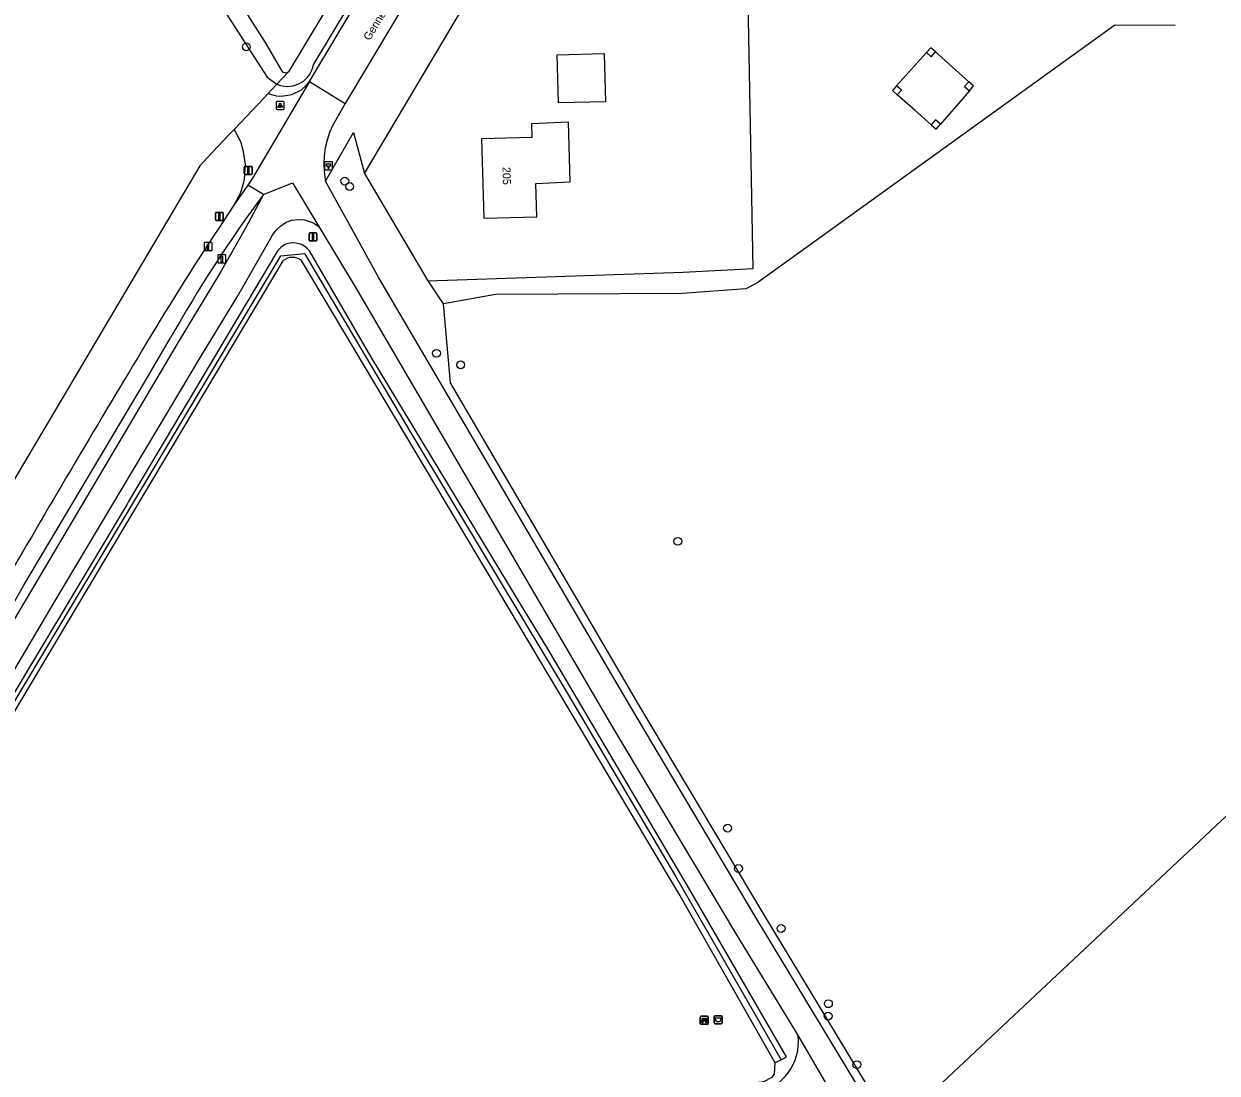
# Model space of a CAD drawing. Extents: x 160203 to 161526, y 379529 to 381797.
# Drawn here: x 160317.7 to 160466.9, y 379846.1 to 379977.3 of the extents above; entities that cross this region are included whole.
import ezdxf

# ---------------------------------------------------------------- set-up
doc = ezdxf.new("R2010")
doc.units = 0
for name, color, linetype in [('IMGEO_Afvalbak', 7, 'Continuous'), ('IMGEO_Bank', 7, 'Continuous'), ('IMGEO_Berm_groen', 7, 'Continuous'), ('IMGEO_Boom', 7, 'Continuous'), ('IMGEO_Fietspad_gesloten', 7, 'Continuous'), ('IMGEO_Grasland_agrarisch', 7, 'Continuous'), ('IMGEO_Grasland_overig', 7, 'Continuous'), ('IMGEO_Groenvoorziening', 7, 'Continuous'), ('IMGEO_Hectometerpaal', 7, 'Continuous'), ('IMGEO_Hek', 7, 'Continuous'), ('IMGEO_Hoogspanningsmast', 7, 'Continuous'), ('IMGEO_Lichtpunt', 7, 'Continuous'), ('IMGEO_Loofbos', 7, 'Continuous'), ('IMGEO_Naaldbos', 7, 'Continuous'), ('IMGEO_Openbare_ruimte_label', 7, 'Continuous'), ('IMGEO_Paal', 7, 'Continuous'), ('IMGEO_Pand', 7, 'Continuous'), ('IMGEO_Pand_nummerreeks', 7, 'Continuous'), ('IMGEO_Rijbaan_lokaal_gesloten', 7, 'Continuous'), ('IMGEO_Rijbaan_lokaal_halfverhard', 7, 'Continuous'), ('IMGEO_Rijbaan_lokaal_onverhard', 7, 'Continuous'), ('IMGEO_Rijbaan_lokaal_open', 7, 'Continuous'), ('IMGEO_Verkeersbordpaal', 7, 'Continuous'), ('IMGEO_Waterloop', 7, 'Continuous')]:
    doc.layers.add(name, color=color, linetype=linetype)

msp = doc.modelspace()

# ---------------------------------------------------------------- linework, layer by layer
at = {"layer": 'IMGEO_Afvalbak'}
for p, q in [((160404.02, 379852.39), (160404.02, 379853.19)), ((160404.02, 379853.19), (160404.02, 379852.39)), ((160404.12, 379853.29), (160404.91, 379853.29)), ((160404.91, 379853.29), (160404.12, 379853.29)), ((160405.01, 379853.19), (160405.01, 379852.39)), ((160405.01, 379852.39), (160405.01, 379853.19)), ((160404.91, 379852.29), (160404.12, 379852.29)), ((160404.12, 379852.29), (160404.91, 379852.29))]:
    msp.add_line(p, q, dxfattribs=at)
msp.add_lwpolyline([(160404.16, 379853.01), (160404.87, 379853.01), (160404.72, 379852.54), (160404.31, 379852.54), (160404.16, 379853.01)], dxfattribs=at)
for centre, start, end in [((160404.12, 379853.19), 90, 180), ((160404.12, 379853.19), 90, 180), ((160404.91, 379853.19), 0, 90), ((160404.91, 379853.19), 360, 90), ((160404.12, 379852.39), 180, 270), ((160404.12, 379852.39), 180, 270), ((160404.91, 379852.39), 270, 0), ((160404.91, 379852.39), 270, 0)]:
    msp.add_arc(centre, 0.1, start, end, dxfattribs=at)
at = {"layer": 'IMGEO_Bank'}
for p, q in [((160402.29, 379852.29), (160402.29, 379853.13)), ((160402.29, 379853.13), (160402.29, 379852.29)), ((160402.36, 379853.22), (160403.2, 379853.22)), ((160403.2, 379853.22), (160402.36, 379853.22)), ((160403.29, 379853.14), (160403.29, 379852.3)), ((160403.29, 379852.3), (160403.29, 379853.14)), ((160403.21, 379852.22), (160402.37, 379852.22)), ((160402.37, 379852.22), (160403.21, 379852.22)), ((160402.98, 379852.62), (160402.59, 379852.62)), ((160402.6, 379852.72), (160402.6, 379852.83)), ((160402.64, 379852.83), (160402.64, 379852.72)), ((160402.93, 379852.84), (160402.65, 379852.84)), ((160402.65, 379852.72), (160402.93, 379852.72)), ((160402.94, 379852.72), (160402.94, 379852.83)), ((160402.98, 379852.83), (160402.98, 379852.72))]:
    msp.add_line(p, q, dxfattribs=at)
for points in [[(160402.54, 379852.62), (160402.39, 379852.62), (160402.5, 379852.72), (160402.59, 379852.72)], [(160402.59, 379852.84), (160402.5, 379852.84), (160402.5, 379853), (160403.07, 379853), (160403.07, 379852.84), (160402.99, 379852.84)], [(160402.59, 379852.61), (160402.59, 379852.4), (160402.54, 379852.4), (160402.54, 379852.61)], [(160402.99, 379852.72), (160403.07, 379852.72), (160403.18, 379852.62), (160403.04, 379852.62)], [(160403.03, 379852.61), (160403.03, 379852.4), (160402.99, 379852.4), (160402.99, 379852.61)]]:
    msp.add_lwpolyline(points, dxfattribs=at)
for centre, radius, start, end in [((160402.37, 379853.14), 0.0779, 92.4484, 184.2845), ((160402.37, 379853.14), 0.0779, 92.4484, 184.2845), ((160403.21, 379853.14), 0.0779, 2.4484, 94.2845), ((160403.21, 379853.14), 0.0779, 2.4484, 94.2845), ((160402.37, 379852.3), 0.0779, 182.4484, 274.2845), ((160402.37, 379852.3), 0.0779, 182.4484, 274.2845), ((160402.54, 379852.61), 0.00671, 2.8957, 87.1043), ((160402.59, 379852.83), 0.00671, 2.8957, 87.1043), ((160402.59, 379852.72), 0.00671, 272.8957, 357.1043), ((160402.59, 379852.61), 0.00671, 92.8957, 177.1043), ((160402.65, 379852.83), 0.00671, 92.8957, 177.1043), ((160402.65, 379852.72), 0.00671, 182.8957, 267.1043), ((160402.93, 379852.83), 0.00671, 2.8957, 87.1043), ((160402.93, 379852.72), 0.00671, 272.8957, 357.1043), ((160402.99, 379852.83), 0.00671, 92.8957, 177.1043), ((160402.99, 379852.72), 0.00671, 182.8957, 267.1043), ((160402.98, 379852.61), 0.00671, 2.8957, 87.1043), ((160403.04, 379852.61), 0.00671, 92.8957, 177.1043), ((160403.21, 379852.3), 0.0779, 272.4484, 4.2845), ((160403.21, 379852.3), 0.0779, 272.4484, 4.2845)]:
    msp.add_arc(centre, radius, start, end, dxfattribs=at)
at = {"layer": 'IMGEO_Berm_groen'}
for points in [[(160360.33, 379958.58), (160382.33, 379995.65)], [(160348.28, 379968.57), (160349.28, 379968.28), (160349.93, 379968.22), (160351.24, 379968.42), (160352.43, 379969.02), (160353.08, 379969.61), (160353.43, 379970.05)], [(160349.37, 379969.72), (160348.7, 379969.01), (160348.28, 379968.57)], [(160355.43, 379957.61), (160358.93, 379963.68), (160360.33, 379958.58)]]:
    msp.add_lwpolyline(points, dxfattribs=at)
at = {"layer": 'IMGEO_Boom'}
for centre in [(160345.55, 379974.39), (160357.85, 379957.61), (160358.46, 379956.93), (160369.31, 379936.09), (160372.33, 379934.65), (160399.48, 379912.59), (160405.69, 379876.74), (160407.06, 379871.69), (160412.39, 379864.2), (160418.3, 379854.79), (160418.26, 379853.24), (160421.86, 379847.18)]:
    msp.add_circle(centre, 0.489, dxfattribs=at)
at = {"layer": 'IMGEO_Fietspad_gesloten'}
for points in [[(160345.72, 379957.12), (160343.99, 379954.59)], [(160334.19, 379939.24), (160333.69, 379938.42)], [(160317.74, 379907.1), (160332.84, 379932.52), (160336.07, 379938.01)]]:
    msp.add_lwpolyline(points, dxfattribs=at)
for centre, radius, start, end in [((160633.93, 379758.64), 349.94, 145.9484, 148.9301), ((160487.24, 379852.9), 173.48, 143.5655, 150.6206), ((162045.74, 378904.9), 1999.82, 148.88178, 149.88066), ((159620.75, 380295.57), 797.94, 328.33041, 330.86665)]:
    msp.add_arc(centre, radius, start, end, dxfattribs=at)
at = {"layer": 'IMGEO_Grasland_agrarisch'}
msp.add_lwpolyline([(160348.28, 379968.57), (160347.68, 379967.93), (160344.8, 379964.89), (160344.03, 379964.08)], dxfattribs=at)
at = {"layer": 'IMGEO_Grasland_overig'}
for points in [[(160368.22, 379945.15), (160400.15, 379946.25), (160408.91, 379946.67), (160407.99, 379995.8), (160400.24, 379995.97), (160382.33, 379995.65)], [(160576.07, 379979.7), (160426.4, 379839.14)], [(160426.83, 379969.52), (160430.56, 379973.7)], [(160431.69, 379973.76), (160435.85, 379970.04)], [(160431.16, 379964.64), (160429.14, 379966.42), (160426.89, 379968.4)], [(160435.92, 379968.9), (160432.29, 379964.72)], [(160368.22, 379945.15), (160370.16, 379942.26), (160371, 379932.38), (160383.71, 379910.71), (160394.58, 379892.15), (160410.1, 379866.11), (160426.4, 379839.14)], [(160412.38, 379847.79), (160411.66, 379847.42)]]:
    msp.add_lwpolyline(points, dxfattribs=at)
at = {"layer": 'IMGEO_Groenvoorziening'}
msp.add_lwpolyline([(160360.33, 379958.58), (160368.22, 379945.15)], dxfattribs=at)
at = {"layer": 'IMGEO_Hectometerpaal'}
for p, q in [((160355.33, 379959.95), (160355.33, 379959.11)), ((160355.33, 379959.95), (160355.33, 379959.11)), ((160356.24, 379960.04), (160355.4, 379960.04)), ((160356.24, 379960.04), (160355.4, 379960.04)), ((160355.41, 379959.04), (160356.25, 379959.04)), ((160355.41, 379959.04), (160356.25, 379959.04)), ((160356.33, 379959.12), (160356.33, 379959.96)), ((160356.33, 379959.12), (160356.33, 379959.96))]:
    msp.add_line(p, q, dxfattribs=at)
msp.add_lwpolyline([(160355.85, 379959.18), (160355.79, 379959.18), (160355.79, 379959.49), (160355.57, 379959.49), (160355.57, 379959.75), (160356.07, 379959.75), (160356.07, 379959.49), (160355.85, 379959.49), (160355.85, 379959.18)], dxfattribs=at)
for centre, start, end in [((160355.41, 379959.96), 92.4484, 184.2845), ((160355.41, 379959.96), 92.4484, 184.2845), ((160355.41, 379959.12), 182.4484, 274.2845), ((160355.41, 379959.12), 182.4484, 274.2845), ((160356.25, 379959.96), 2.4484, 94.2845), ((160356.25, 379959.96), 2.4484, 94.2845), ((160356.25, 379959.12), 272.4484, 4.2845), ((160356.25, 379959.12), 272.4484, 4.2845)]:
    msp.add_arc(centre, 0.0779, start, end, dxfattribs=at)
at = {"layer": 'IMGEO_Hek'}
for points in [[(160461.66, 379977.08), (160454.11, 379977.11), (160414.7, 379948.7)], [(160349.37, 379969.72), (160350.83, 379971.26)], [(160348.28, 379968.57), (160348.7, 379969.01), (160349.37, 379969.72)], [(160344.03, 379964.08), (160344.8, 379964.89), (160347.68, 379967.93), (160348.28, 379968.57)], [(160339.72, 379959.52), (160340.64, 379960.5), (160343.37, 379963.38), (160344.03, 379964.08)], [(160414.7, 379948.7), (160409.37, 379944.86), (160407.99, 379944.15), (160400.02, 379943.55), (160376.68, 379943.45), (160370.9, 379942.4), (160370.16, 379942.26)]]:
    msp.add_lwpolyline(points, dxfattribs=at)
at = {"layer": 'IMGEO_Hoogspanningsmast'}
for points in [[(160431.69, 379973.76), (160431.1, 379974.29), (160430.56, 379973.7)], [(160430.56, 379973.7), (160431.16, 379973.16), (160431.69, 379973.76)], [(160426.83, 379969.52), (160426.29, 379968.92), (160426.89, 379968.4)], [(160426.89, 379968.4), (160427.43, 379968.99), (160426.83, 379969.52)], [(160435.85, 379970.04), (160435.33, 379969.43), (160435.92, 379968.9)], [(160435.92, 379968.9), (160436.45, 379969.5), (160435.85, 379970.04)], [(160432.29, 379964.72), (160431.68, 379965.25), (160431.16, 379964.64)], [(160431.16, 379964.64), (160431.76, 379964.11), (160432.29, 379964.72)]]:
    msp.add_lwpolyline(points, dxfattribs=at)
at = {"layer": 'IMGEO_Lichtpunt'}
for p, q in [((160349.27, 379967.46), (160349.27, 379966.65)), ((160349.27, 379967.46), (160349.27, 379966.65)), ((160350.17, 379967.55), (160349.36, 379967.55)), ((160350.17, 379967.55), (160349.36, 379967.55)), ((160349.36, 379966.55), (160350.17, 379966.55)), ((160349.36, 379966.55), (160350.17, 379966.55)), ((160350.27, 379966.65), (160350.27, 379967.46)), ((160350.27, 379966.65), (160350.27, 379967.46))]:
    msp.add_line(p, q, dxfattribs=at)
for points in [[(160349.64, 379967.12), (160349.68, 379967.09), (160349.5, 379966.83), (160349.46, 379966.86), (160349.64, 379967.12)], [(160349.75, 379967.07), (160349.79, 379967.07), (160349.79, 379966.75), (160349.75, 379966.75), (160349.75, 379967.07)], [(160349.86, 379967.09), (160349.89, 379967.12), (160350.08, 379966.86), (160350.04, 379966.83), (160349.86, 379967.09)]]:
    msp.add_lwpolyline(points, dxfattribs=at)
msp.add_circle((160349.77, 379967.25), 0.0994, dxfattribs=at)
for centre, start, end in [((160349.36, 379967.46), 90, 180), ((160349.36, 379967.46), 90, 180), ((160349.36, 379966.65), 180, 270), ((160349.36, 379966.65), 180, 270), ((160350.17, 379967.46), 0, 90), ((160350.17, 379967.46), 0, 90), ((160350.17, 379966.65), 270, 0), ((160350.17, 379966.65), 270, 360)]:
    msp.add_arc(centre, 0.0946, start, end, dxfattribs=at)
at = {"layer": 'IMGEO_Loofbos'}
for points in [[(160344.03, 379964.08), (160343.37, 379963.38), (160340.64, 379960.5), (160339.72, 379959.52), (160309.99, 379909.32), (160298.15, 379889.57), (160271.43, 379843.62), (160269.94, 379840.82), (160269.1, 379840.82)], [(160344.03, 379964.08), (160344.58, 379963.06), (160344.85, 379962.42), (160345.12, 379961.53), (160345.38, 379959.7), (160345.26, 379957.86), (160345.05, 379956.96), (160344.76, 379956.08), (160343.99, 379954.59)]]:
    msp.add_lwpolyline(points, dxfattribs=at)
at = {"layer": 'IMGEO_Naaldbos'}
for points in [[(160350.12, 379947.64), (160330.19, 379914.23), (160290.49, 379847.67), (160289.95, 379848.06)], [(160411.66, 379847.42), (160399.59, 379868.58), (160378.38, 379904.17), (160352.45, 379947.67)], [(160289.38, 379848.46), (160285.52, 379842.88), (160285.39, 379842.42), (160285.36, 379841.67), (160285.4, 379841.12), (160285.57, 379840.56), (160286.32, 379839.16), (160293.26, 379839.13), (160321.57, 379840.37), (160326.56, 379840.64), (160395.84, 379844.33), (160408.84, 379844.89), (160410.21, 379845.08), (160411.28, 379845.6), (160411.57, 379846), (160411.66, 379847.42)]]:
    msp.add_lwpolyline(points, dxfattribs=at)
msp.add_arc((160351.3, 379946.26), 1.82, 50.9338, 130.3986, dxfattribs=at)
at = {"layer": 'IMGEO_Paal'}
for p, q in [((160340.26, 379949.85), (160340.26, 379949)), ((160340.26, 379949.85), (160340.26, 379949)), ((160341.17, 379949.93), (160340.33, 379949.93)), ((160341.17, 379949.93), (160340.33, 379949.93)), ((160340.34, 379948.93), (160341.18, 379948.93)), ((160340.34, 379948.93), (160341.18, 379948.93)), ((160341.26, 379949.01), (160341.26, 379949.86)), ((160341.26, 379949.01), (160341.26, 379949.86)), ((160341.97, 379948.31), (160341.97, 379947.47)), ((160341.97, 379948.31), (160341.97, 379947.47)), ((160342.89, 379948.39), (160342.05, 379948.39)), ((160342.89, 379948.39), (160342.05, 379948.39)), ((160342.06, 379947.39), (160342.9, 379947.39)), ((160342.06, 379947.39), (160342.9, 379947.39)), ((160342.97, 379947.48), (160342.97, 379948.32)), ((160342.97, 379947.48), (160342.97, 379948.32))]:
    msp.add_line(p, q, dxfattribs=at)
for points in [[(160340.67, 379949.74), (160340.83, 379949.74), (160340.83, 379949.01), (160340.67, 379949.01), (160340.67, 379949.74)], [(160342.39, 379948.21), (160342.55, 379948.21), (160342.55, 379947.47), (160342.39, 379947.47), (160342.39, 379948.21)]]:
    msp.add_lwpolyline(points, dxfattribs=at)
for centre, start, end in [((160340.34, 379949.85), 92.4484, 184.2845), ((160340.34, 379949.85), 92.4484, 184.2845), ((160340.34, 379949.01), 182.4484, 274.2845), ((160340.34, 379949.01), 182.4484, 274.2845), ((160341.18, 379949.85), 2.4484, 94.2845), ((160341.18, 379949.85), 2.4484, 94.2845), ((160341.18, 379949.01), 272.4484, 4.2845), ((160341.18, 379949.01), 272.4484, 4.2845), ((160342.05, 379948.32), 92.4484, 184.2845), ((160342.05, 379948.32), 92.4484, 184.2845), ((160342.05, 379947.47), 182.4484, 274.2845), ((160342.05, 379947.47), 182.4484, 274.2845), ((160342.9, 379948.32), 2.4484, 94.2845), ((160342.9, 379948.32), 2.4484, 94.2845), ((160342.9, 379947.47), 272.4484, 4.2845), ((160342.9, 379947.47), 272.4484, 4.2845)]:
    msp.add_arc(centre, 0.0779, start, end, dxfattribs=at)
at = {"layer": 'IMGEO_Pand'}
for points in [[(160390.27, 379973.55), (160390.43, 379967.53), (160384.55, 379967.38), (160384.39, 379973.4), (160390.27, 379973.55)], [(160385.81, 379964.96), (160381.18, 379964.79), (160381.22, 379963.05), (160374.95, 379962.89), (160375.21, 379952.97), (160381.85, 379953.15), (160381.74, 379957.31), (160386.01, 379957.54), (160385.81, 379964.96)]]:
    msp.add_lwpolyline(points, dxfattribs=at)
at = {"layer": 'IMGEO_Rijbaan_lokaal_gesloten'}
for points in [[(160353.43, 379970.05), (160346.32, 379958), (160345.72, 379957.12)], [(160353.43, 379970.05), (160357.91, 379967.3)], [(160357.91, 379967.3), (160356.34, 379964.6), (160355.94, 379963.68), (160355.63, 379962.74), (160355.41, 379961.77), (160355.27, 379960.79), (160355.22, 379959.8), (160355.26, 379958.81), (160355.39, 379957.82), (160355.43, 379957.61)], [(160424.62, 379840.15), (160409.24, 379865.59), (160393.72, 379891.65), (160383.03, 379909.88), (160362.12, 379945.53), (160355.43, 379957.61)], [(160347.67, 379955.94), (160345.72, 379957.12)], [(160347.67, 379955.94), (160351.32, 379957.41), (160354.6, 379951.94)], [(160354.6, 379951.94), (160359.38, 379943.97), (160380.87, 379907.23), (160391.07, 379889.78), (160406.69, 379863.63), (160414.5, 379850.79)], [(160414.5, 379850.79), (160421.59, 379838.6)]]:
    msp.add_lwpolyline(points, dxfattribs=at)
at = {"layer": 'IMGEO_Rijbaan_lokaal_halfverhard'}
msp.add_arc((160408.08, 379850), 6.47, 280.2664, 6.9736, dxfattribs=at)
at = {"layer": 'IMGEO_Rijbaan_lokaal_onverhard'}
for points in [[(160347.67, 379955.94), (160345.43, 379951.75), (160342.31, 379946.22), (160337.02, 379937.5), (160318.7, 379906.49), (160300.69, 379876.22), (160281.38, 379844.94), (160279.77, 379841.98), (160277.86, 379839.2), (160275.67, 379836.64), (160273.99, 379835.07)], [(160286.85, 379837.88), (160286.07, 379838.26), (160285.42, 379838.76), (160284.88, 379839.39), (160284.49, 379840.12), (160284.26, 379840.91), (160284.2, 379841.74), (160284.43, 379842.95), (160284.79, 379843.7), (160288.19, 379849.3), (160303.47, 379874.46), (160321.52, 379904.95), (160339.94, 379935.83), (160344.47, 379943.28), (160348.83, 379950.84), (160349.27, 379951.49), (160349.84, 379952.04), (160350.51, 379952.46), (160351.25, 379952.72), (160352.03, 379952.83), (160352.82, 379952.78), (160353.94, 379952.39), (160354.6, 379951.94)]]:
    msp.add_lwpolyline(points, dxfattribs=at)
at = {"layer": 'IMGEO_Rijbaan_lokaal_open'}
for points in [[(160353.43, 379970.05), (160371.33, 380000), (160375.27, 380006.61), (160373.71, 380007.73), (160373.06, 380008.26)], [(160375.89, 379997.42), (160357.91, 379967.3)]]:
    msp.add_lwpolyline(points, dxfattribs=at)
at = {"layer": 'IMGEO_Verkeersbordpaal'}
for p, q in [((160345.29, 379958.55), (160345.29, 379959.35)), ((160345.29, 379959.35), (160345.29, 379958.55)), ((160345.39, 379959.45), (160346.18, 379959.45)), ((160346.18, 379959.45), (160345.39, 379959.45)), ((160346.28, 379959.35), (160346.28, 379958.55)), ((160346.28, 379958.55), (160346.28, 379959.35)), ((160346.18, 379958.45), (160345.39, 379958.45)), ((160345.39, 379958.45), (160346.18, 379958.45)), ((160341.67, 379952.8), (160341.67, 379953.6)), ((160341.67, 379953.6), (160341.67, 379952.8)), ((160341.77, 379953.7), (160342.56, 379953.7)), ((160342.56, 379953.7), (160341.77, 379953.7)), ((160342.66, 379953.6), (160342.66, 379952.8)), ((160342.66, 379952.8), (160342.66, 379953.6)), ((160342.56, 379952.7), (160341.77, 379952.7)), ((160341.77, 379952.7), (160342.56, 379952.7)), ((160353.38, 379950.23), (160353.38, 379951.03)), ((160353.38, 379951.03), (160353.38, 379950.23)), ((160353.48, 379951.13), (160354.27, 379951.13)), ((160354.27, 379951.13), (160353.48, 379951.13)), ((160354.27, 379950.13), (160353.48, 379950.13)), ((160353.48, 379950.13), (160354.27, 379950.13)), ((160354.37, 379951.03), (160354.37, 379950.23)), ((160354.37, 379950.23), (160354.37, 379951.03))]:
    msp.add_line(p, q, dxfattribs=at)
for points in [[(160345.71, 379959.32), (160345.86, 379959.32), (160345.86, 379958.57), (160345.71, 379958.57), (160345.71, 379959.32)], [(160342.09, 379953.58), (160342.24, 379953.58), (160342.24, 379952.83), (160342.09, 379952.83), (160342.09, 379953.58)], [(160353.8, 379951.01), (160353.95, 379951.01), (160353.95, 379950.26), (160353.8, 379950.26), (160353.8, 379951.01)]]:
    msp.add_lwpolyline(points, dxfattribs=at)
for centre, start, end in [((160345.39, 379959.35), 90, 180), ((160345.39, 379959.35), 90, 180), ((160346.18, 379959.35), 0, 90), ((160346.18, 379959.35), 360, 90), ((160345.39, 379958.55), 180, 270), ((160345.39, 379958.55), 180, 270), ((160346.18, 379958.55), 270, 0), ((160346.18, 379958.55), 270, 0), ((160341.77, 379953.6), 90, 180), ((160341.77, 379953.6), 90, 180), ((160342.56, 379953.6), 0, 90), ((160342.56, 379953.6), 360, 90), ((160341.77, 379952.8), 180, 270), ((160341.77, 379952.8), 180, 270), ((160342.56, 379952.8), 270, 0), ((160342.56, 379952.8), 270, 0), ((160353.48, 379951.03), 90, 180), ((160353.48, 379951.03), 90, 180), ((160353.48, 379950.23), 180, 270), ((160353.48, 379950.23), 180, 270), ((160354.27, 379951.03), 0, 90), ((160354.27, 379951.03), 360, 90), ((160354.27, 379950.23), 270, 0), ((160354.27, 379950.23), 270, 0)]:
    msp.add_arc(centre, 0.1, start, end, dxfattribs=at)
at = {"layer": 'IMGEO_Waterloop'}
for points in [[(160373.96, 380005.5), (160370.65, 380000), (160353.95, 379972.21)], [(160368.12, 380000), (160350.83, 379971.26), (160350.52, 379971.11), (160350.09, 379971.23), (160347.92, 379974.93), (160340.63, 379986.39), (160337.45, 379991.38)], [(160337.45, 379991.38), (160335.78, 379989.85), (160340.15, 379983.05), (160348.14, 379970.62), (160349.37, 379969.72)], [(160349.27, 379948.61), (160330.82, 379917.56), (160330.63, 379917.24), (160289.38, 379848.46)], [(160289.95, 379848.06), (160349.84, 379948.27), (160352.83, 379948.55), (160366.11, 379926.16), (160385.68, 379893.58), (160399.2, 379870.72), (160412.38, 379847.79)], [(160412.38, 379847.79), (160413.05, 379848.15), (160401.12, 379868.81), (160383.21, 379899.13), (160379.4, 379905.43), (160361.1, 379935.68), (160353.43, 379948.9)]]:
    msp.add_lwpolyline(points, dxfattribs=at)
for centre, radius, start, end in [((160350.67, 379972.78), 3.33, 246.9734, 343.0394), ((160350.74, 379972.77), 3.25, 342.8613, 350.2007), ((160351.75, 379947.14), 2.88, 113.5635, 149.3866), ((160351.37, 379947.27), 2.62, 38.3735, 107.2592)]:
    msp.add_arc(centre, radius, start, end, dxfattribs=at)

# ---------------------------------------------------------------- texts
at = {"layer": 'IMGEO_Openbare_ruimte_label'}
msp.add_text('Genneperweg', height=1, rotation=58.4563, dxfattribs=at).set_placement((160360.95, 379975.09))
at = {"layer": 'IMGEO_Pand_nummerreeks'}
msp.add_text('205', height=1, rotation=271.5009, dxfattribs=at).set_placement((160377.56, 379959.37))

doc.saveas('drawing.dxf')
